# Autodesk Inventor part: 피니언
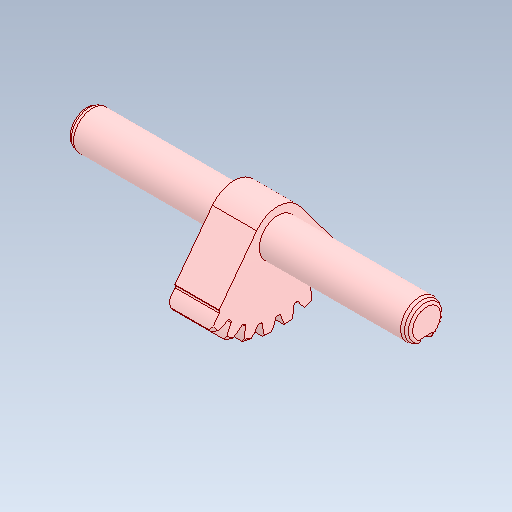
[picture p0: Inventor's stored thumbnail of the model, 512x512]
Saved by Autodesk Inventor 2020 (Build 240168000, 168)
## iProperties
Created: 2024-05
Part Number: 피니언
Material: 강철, 탄소
Document SubType Name: Modeling
Designer: oem
Density: 7.85 g/cm^3
Appearance: 기본값
Author: jhkim
Sending System: Autodesk Inventor 2025
Preprocessor: ST-DEVELOPER v20
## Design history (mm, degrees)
feature "솔리드1"
node "솔리드2"
